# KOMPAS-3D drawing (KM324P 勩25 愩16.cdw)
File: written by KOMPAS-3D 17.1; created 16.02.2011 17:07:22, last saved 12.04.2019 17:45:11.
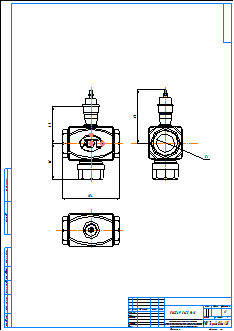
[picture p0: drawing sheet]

Title block, sheet 1: name: KM324P Ду25 Ру16; material: Внимание! Данный продукт является объектом авторского права ООО «Торговый Дом АДЛ». / Запрещается изменение, копирование, распространение / (в том числе путем копирования на другие сайты и ресурсы в Интернете) / или любое иное использование информации и объектов без предварительного / согласия правообладателя (ООО «Торговый Дом АДЛ»).; scale: 1:1; sheets: 1; organisation: ООО "Торговый дом АДЛ"; sheet format: A2; stored path: \\adlc.lan\data\АДЛ_ПКД\3D-модели\ADL production\Клапаны ГРАНРЕГ\Трёхходовой клапан KM324P\KOMPAS 2D\KM324P Ду25 Ру16.cdw

Views: Спереди 1, Проекционный вид 2, Проекционный вид 3
Dimensions and other numbers on the sheet: 104; 65; 67; 96; 1; 1:1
